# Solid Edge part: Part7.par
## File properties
Author: Deepak Maini
Template: Normal.par
Last saved by: MYPC
Revision: 8
Application: Solid Edge
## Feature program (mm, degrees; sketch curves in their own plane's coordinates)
sketch for "unnamed Protrusion 1" plane through (0, 0, 0) normal (0, 0, 1) x-axis (1, 0, 0)
  line (-37.8084, 8.3373) -> (-32.6389, -42.9666)
  arc centre (-23.6843, -42.0643) radius 9 from (-32.6389, -42.9666) to (-23.6843, -51.0643) ccw
  line (-23.6843, -51.0643) -> (23.6843, -51.0643)
  arc centre (23.6843, -42.0643) radius 9 from (32.6389, -42.9666) to (23.6843, -51.0643) cw
  line (37.8084, 8.3373) -> (32.6389, -42.9666)
  arc centre (27.8588, 9.3398) radius 10 from (37.8084, 8.3373) to (28.6379, 19.3094) ccw
  line (28.6379, 19.3094) -> (1.1687, 21.4561)
  arc centre (0, 6.5017) radius 15 from (-1.1687, 21.4561) to (1.1687, 21.4561) cw
  line (-28.6379, 19.3094) -> (-1.1687, 21.4561)
  arc centre (-27.8588, 9.3398) radius 10 from (-37.8084, 8.3373) to (-28.6379, 19.3094) cw
extrude "unnamed Protrusion 1" add finite 3.175 along +normal
sketch for "unnamed Protrusion 2" plane through (0, -15.2312, 3.175) normal (0, 0, 1) x-axis (1, 0, 0)
  circle centre (-23.6843, -26.8331) radius 6.5
extrude "unnamed Protrusion 2" add finite 4 along +normal
sketch for "unnamed Hole 1" plane through (-32.8919, -42.1766, 7.175) normal (0, 0, 1) x-axis (0, 1, 0)
  hole centre (0.1123, -9.2076) bore radius 3.5
hole "unnamed Hole 1" through
pattern "unnamed Pattern 1" of "unnamed Protrusion 2", "unnamed Hole 1"
pattern "unnamed Pattern 2"
sketch for "unnamed Protrusion 3" plane through (0, -15.2312, 3.175) normal (0, 0, 1) x-axis (1, 0, 0)
  circle centre (0.501, -0.9588) radius 10.5
extrude "unnamed Protrusion 3" add finite 3.175 along +normal
sketch for "unnamed Hole 2" plane through (0, -12.0628, 6.35) normal (0, 0, 1) x-axis (1, 0, 0)
  hole centre (0.501, -4.1271) bore radius 6
hole "unnamed Hole 2" through
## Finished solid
Body 1: solid body, 35 faces, 58 edges, 20 vertices.
  Faces by surface: cylinder 19, plane 16
  Edges by curve: circle 38, line 20
Bounding box of the edges (mm): 75.718 x 72.566 x 7.175, from (-37.8588, -51.0643, 0) to (37.8588, 21.5017, 7.175).
Cylindrical faces by radius (mm): R3.5 x4, R4.5 x4, R6 x1, R6.5 x4, R9 x2, R10 x2, R10.5 x1, R15 x1
Planar faces by outward normal: +z 10, -y 1, -z 1, oblique 4
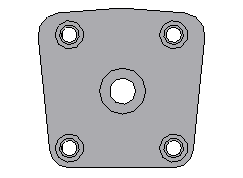
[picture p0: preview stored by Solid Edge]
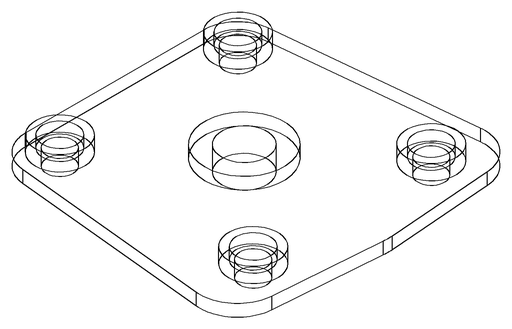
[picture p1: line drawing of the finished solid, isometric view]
